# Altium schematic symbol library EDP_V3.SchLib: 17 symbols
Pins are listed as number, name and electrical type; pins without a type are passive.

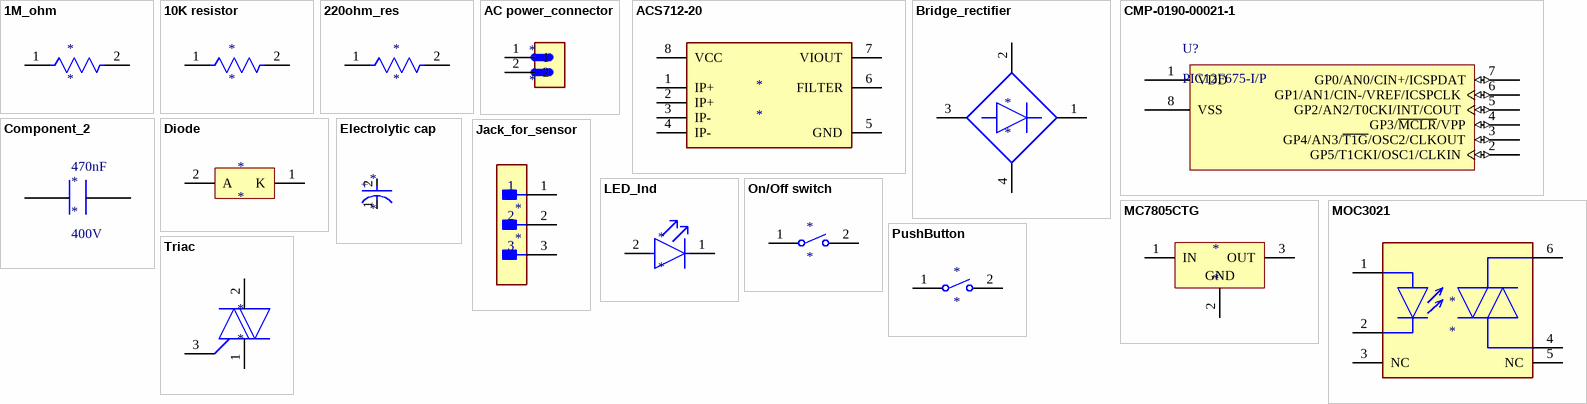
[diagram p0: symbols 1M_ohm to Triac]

## 1M_ohm
designator *
Fixed Resistor, Metal Film, 0.5W, 1000000ohm, 3500V, 1% +/-Tol, 200ppm/Cel, Through Hole Mount; Manufacturer: Vishay BCcomponents; Manufacturer Part Number: HVR3700001004FR500; Power: 500mW; Rated Temperature: 70°C; Value: 1MR; Temperature Coefficient (ppm/Cel): 200; Working Voltage: 3.5kV; Lead Length: 20.25mm; Package Length: 12mm; Lead Diameter: 0.78mm
footprint 1M_om
pins: 1, 2

## 10K resistor
designator *
Fixed Resistor, Thin Film, 0.6W, 1000ohm, 350V, 1% +/-Tol, 50ppm/Cel, Through Hole Mount; Manufacturer: Vishay; Manufacturer Part Number: MRS25000C1001FCT00; Power: 600mW; Rated Temperature: 70°C; Value: 1kR; Temperature Coefficient (ppm/Cel): 50; Additional Feature: RATED AC VOLTAGE: 350V; Lead Length: 28mm; Package Length: 6.5mm; Lead Diameter: 0.6mm
footprint 10K resistor
pins: 1, 2

## 220ohm_res
designator *
Fixed Resistor, Metal Film, 0.25W, 220ohm, 200V, 1% +/-Tol, 50ppm/Cel, Through Hole Mount; Manufacturer: Vishay Beyschlag; Manufacturer Part Number: MBA02040C2200FC100; Power: 400mW; Rated Temperature: 70°C; Value: 220R; Temperature Coefficient (ppm/Cel): 50; Package Length: 3.6mm; Lead Diameter: 0.5mm; Lead Length: 29mm; Reference Standard: AEC-Q200
footprint 220ohm_res
pins: 1, 2

## AC power_connector
designator *
Barrier Strip Terminal Block, 10A, 1 Row(s), 1 Deck(s); Manufacturer: On-Shore Technology; Manufacturer Part Number: OSTTE020104; Fastening Method: SCREW; Additional Feature: STANDARD: UL 94V-0, THERMOPLASTIC; Number of Decks: 1; Number of Ways: 2; Voltage Rating: 125V; Wire/Cable Gauge: 16AWG; Safety Approval: UL,CUL
footprint AC power_connector
pins: 1, 2

## ACS712-20
designator *
pins: 1 IP+, 2 IP+, 3 IP-, 4 IP-, 5 GND (power), 6 FILTER, 7 VIOUT, 8 VCC (power)

## Bridge_rectifier
designator *
Bridge Rectifier Diode, 1 Phase, 0.8A, 1000V V(RRM), Silicon; Manufacturer: Diodes; Manufacturer Part Number: MB10F-13
footprint Bridge rectifier
pins: 1 +, 2 1 ~, 3 -, 4 2 ~

## CMP-0190-00021-1
designator U?, comment PIC12F675-I/P
RISC Microcontroller, 8-Bit, FLASH, PIC CPU, 20MHz, CMOS, PDIP8; Manufacturer: Microchip; Note1: Refer to data sheet (DS41190F) for details of supply voltage range under different conditions.; Package Body Material: Plastic; Number of I/O Lines: 6; Power Supplies: 2.5; Max Supply Current: 15mA; Max Supply Voltage: 5.5V; Min Supply Voltage: 4.5V; Nominal Supply Voltage: 5V; Surface Mount: No; Peripherals: POR,WDT; Package Equivalence Code: DIP8,.3; Qualification Status: Not Qualified
footprint PDIP300-P8 (8-Pin Plastic Dual In-Line Package (PDIP))
pins: 1 VDD (power), 2 GP5/T1CKI/OSC1/CLKIN (io), 3 GP4/AN3/~{T1G}/OSC2/CLKOUT (io), 4 GP3/~{MCLR}/VPP (io), 5 GP2/AN2/T0CKI/INT/COUT (io), 6 GP1/AN1/CIN-/VREF/ICSPCLK (io), 7 GP0/AN0/CIN+/ICSPDAT (io), 8 VSS (power)

## Component_2
designator *  value 470nF  Rated AC Voltage (URac): 400V
Film Capacitor, Polypropylene, 630V, 5% +Tol, 5% -Tol, 0.47uF, Through Hole Mount; Manufacturer: KEMET; Manufacturer Part Number: R76PR3470SE30J; Additional Feature: RATED AC VOLTAGE (V): 400
footprint Capacitor 470nF 400V AC; pin to pad P9>1 P10>2
pins: P9, P10

## Diode
designator *
Rectifier Diode, 1 Phase, 1 Element, 1A, 1000V V(RRM), Silicon, DO-41; Manufacturer: ON Semiconductor; Manufacturer Part Number: 1N4007RLG; Package Body Material: Plastic; Case Connection: Isolated; Forward Voltage: 1.1V; Non-rep Pk Forward Current-Max: 30A; Number of Elements: 1; Rep Pk Reverse Voltage-Max: 1kV; Surface Mount: No; Time @ Peak Reflow Temperature-Max (s): 40s; Qualification Status: Not Qualified
footprint Diode
pins: 1 K, 2 A

## Electrolytic cap
designator *
Aluminum Electrolytic Capacitor, Polarized, Aluminum (wet), 50V, 20% +Tol, 20% -Tol, 220uF, Through Hole Mount; Manufacturer: Panasonic; Manufacturer Part Number: EEU-FR1H221B; Manufacturer Series: FR; Dielectric Material: Aluminium; Leakage Current: 110uA; Ripple Current: 1.155A; Tan Delta: 0.1
footprint Electrolytic cap
pins: 1 C, 2 A

## Jack_for_sensor
designator *
Conn Shrouded Header (4 Sides) HDR 3 POS 2mm Solder RA Side Entry Thru-Hole Box; Manufacturer: JST; Manufacturer Part Number: S3B-PH-K-S(LF)(SN)
footprint Sensor_jack
pins: 1, 2, 3

## LED_Ind
designator *
Single Color LED, Yellow, Tinted Diffused, T-1, 3mm; Manufacturer: Broadcom Avago; Shape: Round; Channels: 1; Forward Current: 7mA; Forward Voltage: 2.7V; Luminous Intensity-Nom: 2.1mcd; Viewing Angle: 50°; Lens Style: Diffused,Tinted; Overall Height: 4.445mm
footprint LED_ind
pins: 1 C, 2 A

## MC7805CTG
designator *
Fixed Positive Standard Regulator, 5VBIPolar; Manufacturer: ON Semiconductor; Manufacturer Part Number: MC7805CTG; Dropout Voltage1-Nom: 2V; Input Voltage Absolute-Max: 35V; Max Supply Voltage: 20V; Min Input Voltage: 7.5V; Channels: 1; Output Current1-Max: 1A; Output Voltage1-Max: 5.25V; Output Voltage1-Min: 4.75V; Output Voltage1-Nom: 5V; Regulator Type: FIXED POSITIVE SINGLE OUTPUT STANDARD REGULATOR; Surface Mount: No; Voltage Tolerance-Max: 5%; Package Equivalence Code: SIP3,.1TB; Time @ Peak Reflow Temperature-Max (s): 40s; Qualification Status: Not Qualified
footprint IC7805
pins: 1 IN (power), 2 GND (power), 3 OUT (power)

## MOC3021
designator *
OPTOISOLATOR 4.17KV TRIAC 6DIP; Manufacturer: ON Semiconductor / Fairchild; Manufacturer Part Number: MOC3021M
footprint DIP6
pins: 1 A, 2 C, 3 NC, 4 1 MAIN TERM., 5 NC, 6 2 MAIN TERM.

## On/Off switch
designator *
Toggle Switch, SPDT, Latched And Momentary, 0.02A, 20VDC, Solder Terminal, Standard Type Actuator, Through Hole-straight; Manufacturer: JST; Manufacturer Part Number: S3B-PH-K-S(LF)(SN); Manufacturer Series: A; Contact AC Max Rating R Load: .02A@20VAC; Contact Current(AC)-Max: 20mA; Contact DC Max Rating R Load: .02A@20VDC; Contact Voltage(AC)-Max: 20V; Body Breadth: 6.86mm; Body Height: 8.89mm; Body Length or Diameter: 12.7mm; Sealing: EPOXY TERMINAL SEALED
pins: 1, 2

## PushButton
designator *
Keypad Switch, 1 Switches, SPST, Momentary, 0.05A, 24VDC, 2.06N, 4 PCB Hole Cnt, Solder Terminal, Through Hole-straight; Manufacturer: TE Connectivity; Manufacturer Part Number: 2-1825910-7; End Contact Plating: Silver; Actuator Color: Black; End Contact Material: Copper Alloy; Actuator Material: Nylon; Contact Current(DC)-Max: 50mA; Contact DC Max Rating R Load: .05A@24VDC; Contact Voltage(DC)-Max: 24V; Actuator Type: Pushbutton; Circuit Configuration: 1X1; Number of Switches: 1; Actuator Angle: 0°; Contact Function: OFF-(ON); Contact Resistance: 0.1mR; Dielectric Withstand Volts: 500VACV; Insulation Resistance: 100MR; PCB Hole Count: 4; Actuator Travel: 0.254mm; Body Breadth: 5.99mm; Body Height: 3.61mm; Actuator Length: 0.37inch
footprint PushButton
pins: 1, 2

## Triac
designator *
Snubberless TRIAC, 600V V(DRM), 16A I(T)RMS, TO-220AB; Manufacturer: STMicroelectronics; Manufacturer Part Number: BTA16-600CWRG; Package Body Material: Plastic; Case Connection: Isolated; Hold Current: 35mA; Leakage Current-Max: 2mA; Number of Elements: 1; Surface Mount: No; Additional Feature: UL RECOGNIZED; Qualification Status: Not Qualified
footprint Triac BTA16-600
pins: 1 A1, 2 A2, 3 G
